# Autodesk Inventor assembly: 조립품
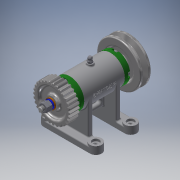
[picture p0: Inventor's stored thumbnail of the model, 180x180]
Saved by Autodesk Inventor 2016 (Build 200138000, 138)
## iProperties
Created: 2015-11
Part Number: 조립품
Document SubType Name: Assembly
Designer: Administrator
Author: Administrator
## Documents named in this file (16)
- D:\451110V1005\451110V1005\조립품.iam
- D:\451110V1005\451110V1005\본체.ipt
- D:\451110V1005\451110V1005\축.ipt
- D:\451110V1005\451110V1005\베어링 15 x 32 x 9.ipt
- D:\451110V1005\451110V1005\커버.ipt
- D:\451110V1005\451110V1005\오일 실 15 25 7.ipt
- D:\451110V1005\451110V1005\와셔 6x11.5.ipt
- D:\451110V1005\451110V1005\볼트 M4 x 12.ipt
- D:\451110V1005\451110V1005\V벨트풀리.ipt
- D:\451110V1005\451110V1005\스퍼기어.ipt
- D:\451110V1005\451110V1005\키 3 x 3 x 12.ipt
- D:\451110V1005\451110V1005\너트 M 8.ipt
- D:\451110V1005\451110V1005\와셔 8x17.ipt
- D:\451110V1005\451110V1005\스프링와셔 8.ipt
- D:\451110V1005\451110V1005\니플 M 6 x 0.75.ipt
- D:\451110V1005\451110V1005\볼트 M 6 x 8.ipt
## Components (11 placed, 3 different names)
1. KS B 2023 6002 - 15 x 32 x 9:1
2. KS B 2023 6002 - 15 x 32 x 9:2
3. ISO 4762 M4 x 12:1
4. ISO 4762 M4 x 12:2
5. ISO 4762 M4 x 12:3
6. ISO 4762 M4 x 12:4
7. ISO 4762 M4 x 12:5
8. ISO 4762 M4 x 12:6
9. ISO 4762 M4 x 12:7
10. ISO 4762 M4 x 12:8
11. V벨트풀리:1
